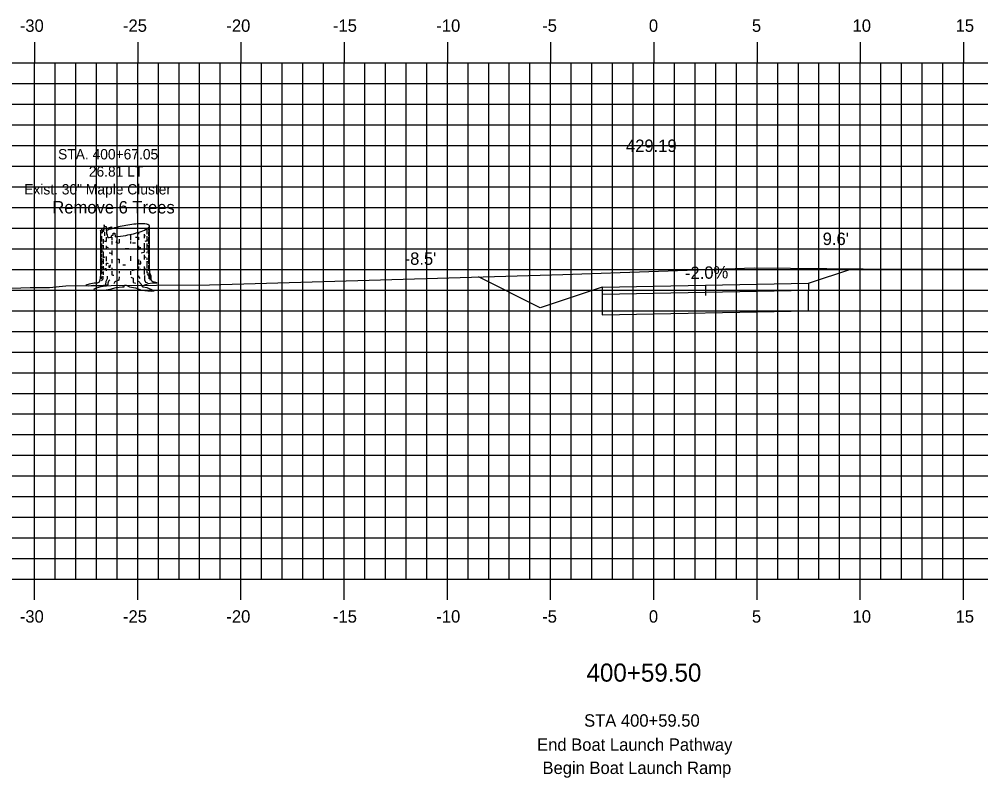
# Model space of a CAD drawing. Extents: x -161 to 764, y 111 to 210.
# Drawn here: x 379.66 to 426.23, y 115.45 to 152.17 of the extents above; entities that cross this region are included whole.
import ezdxf

# ---------------------------------------------------------------- set-up
doc = ezdxf.new("R2010")
doc.units = 0
for name, color, linetype in [('D_Property_Walkway_Paved', 7, 'Continuous'), ('D_Roadway_Centerline_Text', 7, 'Continuous'), ('D_Roadway_SubGrade', 7, 'Continuous'), ('D_Slope_Cut', 7, 'Continuous'), ('D_Text_Monospaced', 7, 'Continuous'), ('D_Text_Standard', 7, 'Continuous'), ('Default', 7, 'Continuous'), ('H_V ANNOTATION', 7, 'Continuous'), ('MAJOR', 7, 'Continuous'), ('MINOR', 7, 'Continuous'), ('S_Roadway_Centerline', 7, 'Continuous'), ('S_Trees_Decid_Pay', 7, 'Continuous')]:
    doc.layers.add(name, color=color, linetype=linetype)

msp = doc.modelspace()

# ---------------------------------------------------------------- linework, layer by layer
at = {"layer": 'D_Property_Walkway_Paved'}
for p, q in [((407.895, 139.196), (417.894, 139.396)), ((417.894, 139.396), (417.894, 139.052)), ((407.895, 139.196), (407.895, 138.852)), ((407.895, 138.852), (417.894, 139.052))]:
    msp.add_line(p, q, dxfattribs=at)
at = {"layer": 'D_Roadway_SubGrade'}
for p, q in [((407.895, 138.852), (407.895, 137.852)), ((417.894, 138.052), (417.894, 139.052)), ((407.895, 137.852), (417.894, 138.052))]:
    msp.add_line(p, q, dxfattribs=at)
at = {"layer": 'D_Slope_Cut'}
for p, q in [((417.894, 139.396), (419.982, 140.092)), ((404.895, 138.196), (401.904, 139.692)), ((407.895, 139.196), (404.895, 138.196))]:
    msp.add_line(p, q, dxfattribs=at)
at = {"layer": 'Default'}
msp.add_line((412.895, 139.296), (412.895, 138.796), dxfattribs=at)
at = {"layer": 'MAJOR'}
for p, q in [((380.395, 151.06), (380.395, 150.058)), ((385.395, 151.06), (385.395, 150.058)), ((390.395, 151.06), (390.395, 150.058)), ((395.395, 151.06), (395.395, 150.058)), ((400.395, 151.06), (400.395, 150.058)), ((405.395, 151.06), (405.395, 150.058)), ((410.395, 151.06), (410.395, 150.058)), ((415.395, 151.06), (415.395, 150.058)), ((420.395, 151.06), (420.395, 150.058)), ((425.395, 151.06), (425.395, 150.058)), ((340.395, 150.058), (480.395, 150.058)), ((340.395, 150.058), (480.395, 150.058)), ((380.395, 125.058), (380.395, 150.058)), ((385.395, 125.058), (385.395, 150.058)), ((390.395, 125.058), (390.395, 150.058)), ((395.395, 125.058), (395.395, 150.058)), ((400.395, 125.058), (400.395, 150.058)), ((405.395, 125.058), (405.395, 150.058)), ((410.395, 125.058), (410.395, 150.058)), ((415.395, 125.058), (415.395, 150.058)), ((420.395, 125.058), (420.395, 150.058)), ((425.395, 125.058), (425.395, 150.058)), ((340.395, 145.058), (480.395, 145.058)), ((340.395, 140.058), (480.395, 140.058)), ((340.395, 135.058), (480.395, 135.058)), ((340.395, 130.058), (480.395, 130.058)), ((340.395, 125.058), (480.395, 125.058)), ((340.395, 125.058), (480.395, 125.058)), ((380.395, 124.056), (380.395, 125.058)), ((385.395, 124.056), (385.395, 125.058)), ((390.395, 124.056), (390.395, 125.058)), ((395.395, 124.056), (395.395, 125.058)), ((400.395, 124.056), (400.395, 125.058)), ((405.395, 124.056), (405.395, 125.058)), ((410.395, 124.056), (410.395, 125.058)), ((415.395, 124.056), (415.395, 125.058)), ((420.395, 124.056), (420.395, 125.058)), ((425.395, 124.056), (425.395, 125.058))]:
    msp.add_line(p, q, dxfattribs=at)
at = {"layer": 'MINOR'}
for p, q in [((381.395, 125.058), (381.395, 150.058)), ((382.395, 125.058), (382.395, 150.058)), ((383.395, 125.058), (383.395, 150.058)), ((384.395, 125.058), (384.395, 150.058)), ((386.395, 125.058), (386.395, 150.058)), ((387.395, 125.058), (387.395, 150.058)), ((388.395, 125.058), (388.395, 150.058)), ((389.395, 125.058), (389.395, 150.058)), ((391.395, 125.058), (391.395, 150.058)), ((392.395, 125.058), (392.395, 150.058)), ((393.395, 125.058), (393.395, 150.058)), ((394.395, 125.058), (394.395, 150.058)), ((396.395, 125.058), (396.395, 150.058)), ((397.395, 125.058), (397.395, 150.058)), ((398.395, 125.058), (398.395, 150.058)), ((399.395, 125.058), (399.395, 150.058)), ((401.395, 125.058), (401.395, 150.058)), ((402.395, 125.058), (402.395, 150.058)), ((403.395, 125.058), (403.395, 150.058)), ((404.395, 125.058), (404.395, 150.058)), ((406.395, 125.058), (406.395, 150.058)), ((407.395, 125.058), (407.395, 150.058)), ((408.395, 125.058), (408.395, 150.058)), ((409.395, 125.058), (409.395, 150.058)), ((411.395, 125.058), (411.395, 150.058)), ((412.395, 125.058), (412.395, 150.058)), ((413.395, 125.058), (413.395, 150.058)), ((414.395, 125.058), (414.395, 150.058)), ((416.395, 125.058), (416.395, 150.058)), ((417.395, 125.058), (417.395, 150.058)), ((418.395, 125.058), (418.395, 150.058)), ((419.395, 125.058), (419.395, 150.058)), ((421.395, 125.058), (421.395, 150.058)), ((422.395, 125.058), (422.395, 150.058)), ((423.395, 125.058), (423.395, 150.058)), ((424.395, 125.058), (424.395, 150.058)), ((340.395, 149.058), (480.395, 149.058)), ((340.395, 148.058), (480.395, 148.058)), ((340.395, 147.058), (480.395, 147.058)), ((340.395, 146.058), (480.395, 146.058)), ((340.395, 144.058), (480.395, 144.058)), ((340.395, 143.058), (480.395, 143.058)), ((340.395, 142.058), (480.395, 142.058)), ((340.395, 141.058), (480.395, 141.058)), ((340.395, 139.058), (480.395, 139.058)), ((340.395, 138.058), (480.395, 138.058)), ((340.395, 137.058), (480.395, 137.058)), ((340.395, 136.058), (480.395, 136.058)), ((340.395, 134.058), (480.395, 134.058)), ((340.395, 133.058), (480.395, 133.058)), ((340.395, 132.058), (480.395, 132.058)), ((340.395, 131.058), (480.395, 131.058)), ((340.395, 129.058), (480.395, 129.058)), ((340.395, 128.058), (480.395, 128.058)), ((340.395, 127.058), (480.395, 127.058)), ((340.395, 126.058), (480.395, 126.058))]:
    msp.add_line(p, q, dxfattribs=at)
at = {"layer": 'S_Roadway_Centerline'}
msp.add_lwpolyline([(340.395, 133.296), (340.882, 133.162), (342.829, 133.127), (344.117, 133.013), (346.843, 135.18), (347.307, 135.532), (347.479, 135.579), (351.296, 136.205), (353.326, 136.466), (355.138, 136.92), (360.341, 137.916), (377.913, 139.096), (380.185, 139.185), (381.124, 139.189), (381.917, 139.256), (386.308, 139.297), (388.872, 139.316), (405.982, 139.809), (415.26, 140.13), (422.294, 140.074), (433.65, 140.066)], dxfattribs=at)
at = {"layer": 'S_Trees_Decid_Pay'}
for p, q in [((385.914, 142.065), (385.914, 141.944)), ((383.639, 141.661), (383.639, 141.407)), ((383.789, 141.861), (383.789, 141.687)), ((383.874, 141.613), (383.874, 141.408)), ((384.135, 141.615), (384.135, 141.495)), ((385.045, 141.752), (385.045, 141.472)), ((385.429, 141.853), (385.429, 141.767)), ((385.429, 141.626), (385.429, 141.487)), ((385.701, 141.767), (385.701, 141.575)), ((385.833, 142.02), (385.833, 141.767)), ((385.833, 141.67), (385.833, 141.407)), ((385.914, 141.892), (385.914, 141.678)), ((385.914, 141.633), (385.914, 141.295)), ((383.639, 141.309), (383.639, 140.84)), ((383.725, 141.515), (383.725, 141.304)), ((383.725, 141.238), (383.725, 141.09)), ((383.874, 141.201), (383.874, 141.046)), ((384.135, 141.443), (384.135, 141.258)), ((384.373, 141.343), (384.378, 141.45)), ((384.499, 141.515), (384.499, 141.336)), ((385.045, 141.407), (385.045, 141.304)), ((385.429, 141.201), (385.429, 141.009)), ((385.701, 141.324), (385.701, 141.046)), ((385.833, 141.309), (385.833, 141.001)), ((385.914, 141.178), (385.914, 140.817)), ((383.639, 140.789), (383.639, 140.655)), ((383.725, 140.912), (383.725, 140.612)), ((383.874, 140.683), (383.874, 140.464)), ((384.135, 140.972), (384.135, 140.744)), ((385.045, 140.692), (385.045, 140.472)), ((385.701, 141.001), (385.701, 140.892)), ((385.701, 140.758), (385.701, 140.529)), ((385.833, 140.912), (385.833, 140.846)), ((385.914, 140.781), (385.914, 140.332)), ((383.639, 140.597), (383.639, 140.272)), ((383.639, 140.243), (383.639, 139.823)), ((383.725, 140.575), (383.725, 140.332)), ((383.725, 140.221), (383.725, 140.08)), ((383.874, 140.364), (383.874, 140.243)), ((384.135, 140.546), (384.135, 140.361)), ((384.499, 140.557), (384.499, 140.361)), ((385.429, 140.529), (385.429, 140.321)), ((385.429, 140.2), (385.429, 140)), ((385.701, 140.2), (385.701, 139.817)), ((385.833, 140.612), (385.833, 140.515)), ((385.833, 140.464), (385.833, 140.103)), ((385.914, 140.266), (385.914, 139.984)), ((383.725, 139.949), (383.725, 139.792)), ((383.874, 140.092), (383.874, 139.994)), ((384.135, 140.126), (384.135, 140.049)), ((384.135, 139.972), (384.135, 139.798)), ((384.499, 139.977), (384.499, 139.874)), ((385.045, 139.972), (385.045, 139.798)), ((385.424, 139.743), (385.504, 139.611)), ((385.833, 140.052), (385.833, 139.885)), ((383.643, 139.72), (383.628, 139.603))]:
    msp.add_line(p, q, dxfattribs=at)
for points in [[(383.589, 141.935), (383.589, 139.798), (383.568, 139.657), (383.562, 139.531), (383.519, 139.444), (383.427, 139.395), (383.291, 139.395), (383.047, 139.339), (382.881, 139.29), (383.023, 139.259), (383.26, 139.296), (383.47, 139.284), (383.731, 139.29), (383.855, 139.308), (383.885, 139.265), (383.948, 139.308), (383.849, 139.241), (383.614, 139.216), (383.383, 139.154), (383.253, 139.084), (383.353, 139.04), (383.774, 139.059), (384.053, 139.103), (384.351, 139.179), (384.637, 139.216), (384.742, 139.216), (384.761, 139.296), (384.829, 139.302), (384.996, 139.216), (385.282, 139.16), (385.58, 139.053), (386.04, 139.004), (386.194, 139.016), (385.852, 139.166), (385.648, 139.197), (385.66, 139.271), (385.92, 139.37), (386.095, 139.401), (386.336, 139.413), (386.138, 139.451), (386.076, 139.487), (386.052, 139.574), (386.04, 139.743), (385.994, 139.829), (385.966, 140.07), (385.966, 142.156)], [(383.945, 141.608), (383.937, 141.752), (383.892, 141.744), (383.877, 142.119), (383.783, 142.127), (383.769, 142.207), (383.731, 141.87), (383.686, 141.964), (383.666, 141.81), (383.589, 141.935), (383.595, 141.746)], [(383.967, 141.974), (383.988, 142.082), (384.12, 142.113), (384.127, 142.025)], [(383.589, 141.935), (383.635, 141.958), (383.657, 142.024), (383.709, 142.047), (383.742, 141.972)], [(384.106, 141.613), (384.143, 141.716), (384.209, 141.722), (384.209, 141.804), (384.283, 141.81), (384.308, 141.63)], [(383.997, 140.243), (383.988, 140.169), (384.062, 140.163), (384.077, 140.28)], [(385.542, 140.335), (385.541, 140.412), (385.533, 140.478)], [(385.718, 139.757), (385.718, 139.552), (385.776, 139.442), (385.873, 139.426)], [(385.858, 139.831), (385.93, 139.728), (385.93, 139.603)], [(385.916, 139.912), (385.976, 139.751), (385.99, 139.626), (385.982, 139.529)], [(383.709, 139.728), (383.702, 139.603), (383.62, 139.508)], [(383.855, 139.308), (383.874, 139.487), (383.935, 139.624), (383.929, 139.724)], [(384.046, 139.555), (383.972, 139.487), (383.954, 139.389), (383.948, 139.308)], [(384.498, 139.691), (384.48, 139.537), (384.283, 139.456), (384.238, 139.353)], [(385.063, 139.683), (385.166, 139.632), (385.181, 139.426), (385.284, 139.397)], [(385.648, 139.197), (385.562, 139.339), (385.43, 139.481)]]:
    msp.add_lwpolyline(points, dxfattribs=at)
for centre, radius, start, end in [((385.879, 136.154), 6.126, 100.7779, 107.8613), ((385.879, 136.154), 6.126, 93.6944, 100.7779), ((385.568, 140.971), 1.299, 78.2779, 93.6944), ((385.734, 141.773), 0.48, 69.9843, 78.2779), ((385.607, 142.444), 0.48, 303.2779, 311.5714), ((385.842, 142.07), 0.164, 55.7779, 69.9843), ((385.816, 142.208), 0.164, 311.5714, 325.7779), ((385.874, 142.117), 0.107, 45.9547, 55.7779), ((385.904, 142.148), 0.0645, 33.2779, 45.9547), ((385.863, 142.176), 0.107, 325.7779, 335.6011), ((385.912, 142.153), 0.0544, 22.46, 33.2779), ((385.902, 142.158), 0.0645, 335.6011, 348.2779), ((385.919, 142.156), 0.0467, 10.7779, 22.46), ((385.919, 142.156), 0.0467, 359.0957, 10.7779), ((385.912, 142.156), 0.0544, 348.2779, 359.0957), ((384.398, 140.748), 1.299, 107.8613, 113.3069), ((383.987, 142.907), 1.299, 268.1289, 273.6944), ((383.677, 147.723), 6.126, 273.6944, 274.0246), ((383.677, 147.723), 6.126, 275.9147, 280.7779), ((383.677, 147.723), 6.126, 280.7779, 287.8613), ((384.779, 147.506), 5.916, 274.9514, 276.3087), ((385.157, 143.129), 1.299, 287.8613, 303.2779), ((385.354, 142.918), 1.292, 285.5651, 289.0916), ((385.826, 141.899), 0.166, 301.67, 315), ((385.867, 141.858), 0.109, 315, 324.8263), ((385.902, 141.833), 0.0657, 324.8263, 337.5), ((385.912, 141.829), 0.0554, 337.5, 348.3185), ((383.637, 141.567), 0.0476, 180, 191.6815), ((383.644, 141.569), 0.0554, 191.6815, 202.5), ((383.654, 141.573), 0.0657, 202.5, 215.1737), ((383.689, 141.598), 0.109, 215.1737, 225), ((383.73, 141.638), 0.166, 225, 239.1924), ((383.73, 141.375), 0.166, 237.0378, 239.1924), ((383.893, 141.648), 0.484, 239.1924, 247.5), ((384.202, 142.394), 1.292, 247.5, 248.3537), ((384.202, 142.657), 1.292, 250.6119, 255.2856), ((384.202, 142.394), 1.292, 255.2856, 259.2632), ((384.778, 147.245), 5.916, 266.0776, 267.3043), ((384.778, 147.245), 5.916, 273.5382, 274.8924), ((385.354, 142.657), 1.292, 288.0829, 292.5), ((385.354, 142.394), 1.292, 291.8071, 292.5), ((385.663, 141.648), 0.484, 292.5, 300.8076), ((385.663, 141.911), 0.484, 297.4162, 300.8076), ((385.825, 141.638), 0.166, 300.8076, 315), ((385.825, 141.375), 0.166, 300.8076, 301.6001), ((385.866, 141.598), 0.109, 315, 324.8263), ((385.901, 141.573), 0.0657, 324.8263, 337.5), ((385.911, 141.569), 0.0554, 337.5, 348.3185), ((383.637, 141.046), 0.0476, 180, 191.6815), ((383.637, 140.789), 0.0476, 180, 191.6815), ((383.644, 141.048), 0.0554, 191.6815, 202.5), ((383.644, 140.79), 0.0554, 191.6815, 202.5), ((383.654, 141.052), 0.0657, 202.5, 215.1737), ((383.654, 140.794), 0.0657, 202.5, 215.1737), ((383.689, 141.077), 0.109, 215.1737, 225), ((383.689, 140.819), 0.109, 215.1737, 225), ((383.73, 141.117), 0.166, 225, 239.1924), ((383.73, 140.86), 0.166, 225, 239.1924), ((383.893, 141.39), 0.484, 239.1924, 245.7724), ((384.202, 142.136), 1.292, 247.5, 248.4842), ((384.202, 141.879), 1.292, 247.5, 251.799), ((384.202, 142.136), 1.292, 261.8726, 262.8454), ((384.778, 146.724), 5.916, 262.8454, 263.7595), ((384.778, 146.982), 5.916, 270.1162, 271.7708), ((384.778, 146.982), 5.916, 276.3183, 277.1546), ((385.354, 142.394), 1.292, 277.1546, 278.3662), ((385.354, 142.136), 1.292, 279.2565, 285.6105), ((385.354, 141.879), 1.292, 285.6105, 290.1001), ((385.663, 141.39), 0.484, 294.6372, 300.8076), ((385.825, 141.117), 0.166, 300.8076, 315), ((385.825, 140.86), 0.166, 302.0694, 315), ((385.866, 141.077), 0.109, 315, 324.8263), ((385.866, 140.819), 0.109, 315, 324.8263), ((385.901, 141.052), 0.0657, 324.8263, 337.5), ((385.901, 140.794), 0.0657, 324.8263, 337.5), ((385.911, 141.048), 0.0554, 337.5, 348.3185), ((385.911, 140.79), 0.0554, 337.5, 348.3185), ((383.637, 140.523), 0.0476, 180, 191.6815), ((383.644, 140.525), 0.0554, 191.6815, 202.5), ((383.654, 140.529), 0.0657, 202.5, 215.1737), ((383.689, 140.554), 0.109, 215.1737, 225), ((383.73, 140.594), 0.166, 225, 239.1924), ((383.893, 140.867), 0.484, 239.1924, 247.5), ((384.202, 141.613), 1.292, 247.5, 248.3537), ((384.202, 141.613), 1.292, 255.2856, 259.2463), ((384.778, 146.467), 5.916, 266.2721, 267.3043), ((384.778, 146.201), 5.916, 268.9206, 270), ((384.778, 146.201), 5.916, 270, 270.2757), ((384.778, 146.201), 5.916, 276.3183, 277.1546), ((385.354, 141.613), 1.292, 277.1546, 278.3795), ((385.663, 140.867), 0.484, 292.5, 300.8076), ((385.825, 140.594), 0.166, 300.8076, 302.0694), ((385.825, 140.322), 0.166, 302.0694, 315), ((385.866, 140.282), 0.109, 315, 324.8263), ((385.901, 140.257), 0.0657, 324.8263, 337.5), ((385.911, 140.525), 0.0554, 337.5, 348.3185), ((385.911, 140.253), 0.0554, 337.5, 348.3185), ((383.637, 139.994), 0.0476, 180, 191.6815), ((383.644, 139.996), 0.0554, 191.6815, 202.5), ((383.654, 140), 0.0657, 202.5, 215.1737), ((383.689, 140.025), 0.109, 215.1737, 225), ((383.73, 140.065), 0.166, 225, 239.1924), ((383.893, 140.338), 0.484, 239.1924, 247.5), ((383.893, 140.595), 0.484, 242.734, 247.5), ((384.202, 141.084), 1.292, 247.5, 248.3537), ((384.202, 141.342), 1.292, 251.3664, 255.2856), ((384.778, 145.672), 5.916, 263.7831, 264.7655), ((384.778, 145.93), 5.916, 273.2637, 274.461), ((384.778, 145.93), 5.916, 276.3183, 277.1546), ((385.354, 141.342), 1.292, 277.1546, 278.3662), ((385.354, 141.342), 1.292, 285.6105, 289.1534), ((385.363, 141.088), 1.292, 291.3696, 292.0604), ((385.663, 140.338), 0.484, 292.5, 296.5499)]:
    msp.add_arc(centre, radius, start, end, dxfattribs=at)

# ---------------------------------------------------------------- texts
at = {"layer": 'D_Roadway_Centerline_Text'}
for s, p in [('429.19', (409.046, 145.742)), ('STA 400+59.50', (407.017, 117.921)), ('End Boat Launch Pathway', (404.742, 116.753)), ('Begin Boat Launch Ramp', (405.002, 115.63))]:
    msp.add_text(s, height=0.6, dxfattribs=at).set_placement(p)
at = {"layer": 'D_Text_Monospaced'}
for s, height, p in [('STA. 400+67.05', 0.49998, (381.536, 145.382)), ('26.81 LT', 0.5, (383.026, 144.548)), ('Exist. 30" Maple Cluster', 0.49998, (379.896, 143.685))]:
    msp.add_text(s, height=height, dxfattribs=at).set_placement(p)
at = {"layer": 'D_Text_Standard'}
for s, p in [('Remove 6 Trees', (381.258, 142.765)), ("9.6'", (418.574, 141.237)), ("-8.5'", (398.323, 140.279))]:
    msp.add_text(s, height=0.6, dxfattribs=at).set_placement(p)
msp.add_text('-2.0%', height=0.6, rotation=1.1458, dxfattribs=at).set_placement((411.91, 139.582))
at = {"layer": 'H_V ANNOTATION'}
for s, height, p in [('-30', 0.6, (379.683, 151.558)), ('-25', 0.6, (384.681, 151.558)), ('-20', 0.6, (389.689, 151.558)), ('-15', 0.6, (394.852, 151.558)), ('-10', 0.6, (399.86, 151.558)), ('-5', 0.6, (404.986, 151.558)), ('0', 0.6, (410.154, 151.558)), ('5', 0.6, (415.146, 151.558)), ('10', 0.6, (420.021, 151.558)), ('15', 0.6, (425.013, 151.558)), ('-30', 0.6, (379.683, 122.958)), ('-25', 0.6, (384.681, 122.958)), ('-20', 0.6, (389.689, 122.958)), ('-15', 0.6, (394.852, 122.958)), ('-10', 0.6, (399.86, 122.958)), ('-5', 0.6, (404.986, 122.958)), ('0', 0.6, (410.154, 122.958)), ('5', 0.6, (415.146, 122.958)), ('10', 0.6, (420.021, 122.958)), ('15', 0.6, (425.013, 122.958)), ('400+59.50', 0.875, (407.133, 120.101))]:
    msp.add_text(s, height=height, rotation=360, dxfattribs=at).set_placement(p)

doc.saveas('drawing.dxf')
